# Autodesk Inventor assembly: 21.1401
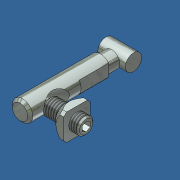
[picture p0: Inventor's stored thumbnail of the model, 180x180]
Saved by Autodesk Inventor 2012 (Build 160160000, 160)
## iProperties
Created: 2006-12
Part Number: 21.1401
Document SubType Name: Assembly
Designer: Andy Moles
Description: MITER CONNECTOR N
Author: Andy Moles
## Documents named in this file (4)
- C:\Andys Backup Data\ANDY'S INVENTOR\INVENTOR LIBRARIES\PARTS LIBRARY\FASTENING ELEMENTS\21.1401 MITER CONNECTOR N.iam
- C:\Andys Backup Data\ANDY'S INVENTOR\INVENTOR LIBRARIES\PARTS LIBRARY\FASTENING ELEMENTS\SUBCOMPONENTS\21.1401 MITER CON N.ipt
- C:\Andys Backup Data\ANDY'S INVENTOR\INVENTOR LIBRARIES\PARTS LIBRARY\FASTENING ELEMENTS\SET SCREWS\SET SCREW M8X20 POINTED FOR MITER CONNECTOR.ipt
- C:\Andys Backup Data\ANDY'S INVENTOR\INVENTOR LIBRARIES\PARTS LIBRARY\FASTENING ELEMENTS\NUTS\21.1351 M8 SQUARE NUT.ipt
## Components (3 placed, 3 different names)
1. 21.1401 MITER CON N:1 — Flush:1, Flush:2, Mate:1, Angle:1
2. SET SCREW M8X20 POINTED FOR MITER CONNECTOR:1 — Flush:1, Flush:2, Mate:1, Insert:1
3. 21.1351 M8 SQUARE NUT:1 — Insert:1, Angle:1
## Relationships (5: Flush 2, Mate 1, Insert 1, Angle 1)
- Flush:1: 21.1401 MITER CON N:1 ↔ SET SCREW M8X20 POINTED FOR MITER CONNECTOR:1
- Flush:2: 21.1401 MITER CON N:1 ↔ SET SCREW M8X20 POINTED FOR MITER CONNECTOR:1
- Mate:1: 21.1401 MITER CON N:1 ↔ SET SCREW M8X20 POINTED FOR MITER CONNECTOR:1
- Insert:1: SET SCREW M8X20 POINTED FOR MITER CONNECTOR:1 ↔ 21.1351 M8 SQUARE NUT:1
- Angle:1: 21.1401 MITER CON N:1 ↔ 21.1351 M8 SQUARE NUT:1
